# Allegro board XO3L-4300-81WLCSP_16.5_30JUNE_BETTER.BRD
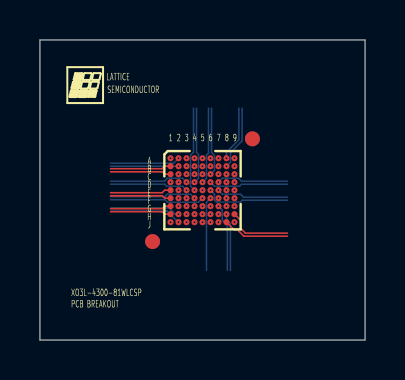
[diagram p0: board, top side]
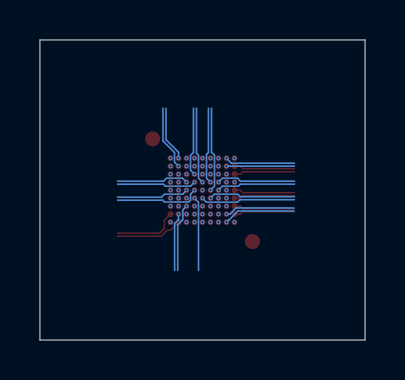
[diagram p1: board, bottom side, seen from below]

Outline 16.28 x 15.02 mm; copper layers: TOP, L2_SIG, L3_PWR/GND, BOTTOM. Coordinates in mm from the lower left corner of the outline.
Outline path: 0,15.02 0,0 16.28,0 16.28,15.02 0,15.02

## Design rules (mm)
net group PB4: nets PB4A PB4B
net group PB7: nets PB7A PB7B
net group PB9: nets PB9A PB9B
net group PB13: nets PB13A PB13B
net group PB15: nets PB15A PB15B
net group PB20: nets PB20A PB20B
net group PB23: nets PB23A PB23B
net group PB24: nets PB24A PB24B
net group PB27: nets PB27A PB27B
net group PB30: nets PB30A PB30B
net group PL4: nets PL4A PL4B
net group PL7: nets PL7A PL7B
net group PL8: nets PL8C PL8D
net group PL15: nets PL15A PL15B
net group PL17: nets PL17A PL17B
net group PL18: nets PL18A PL18B
net group PT9: nets PT9A PT9B
net group PT10: nets PT10A PT10B
net group PT11: nets PT11A PT11B
net group PT13: nets PT13C PT13D
net group PT15: nets PT15C PT15D
net group PT18: nets PT18A PT18B
net group PT19: nets PT19A PT19B
net group PT20: nets PT20C PT20D
net group PT21: nets PT21A PT21B
net group PT22: nets PT22A PT22B
net group PT23: nets PT23C PT23D
net group PT24: nets PT24A PT24B
net group PT25: nets PT25A PT25B
net group PT27: nets PT27A PT27B
net group PT28: nets PT28C PT28D

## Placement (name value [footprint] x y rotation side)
BGA  -  [BGA81N40P9X9_379X369X57B26N]  8.14 7.5 270 top
NOREF  -  []  1.09 11.54 0 top

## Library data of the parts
BGA = BGA81N40P9X9_379X369X57B26N

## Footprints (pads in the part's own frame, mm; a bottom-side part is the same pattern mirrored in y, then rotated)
BGA81N40P9X9_379X369X57B26N
  round 0.75 smd: (-2.57,2.5) (2.57,-2.5)
  round 0.305 smd: A1(-1.6,-1.6) A2(-1.6,-1.2) A3(-1.6,-0.8) A4(-1.6,-0.4) A5(-1.6,0) A6(-1.6,0.4) A7(-1.6,0.8) A8(-1.6,1.2) A9(-1.6,1.6) B1(-1.2,-1.6) B2(-1.2,-1.2) B3(-1.2,-0.8) B4(-1.2,-0.4) B5(-1.2,0) B6(-1.2,0.4) B7(-1.2,0.8) B8(-1.2,1.2) B9(-1.2,1.6) C1(-0.8,-1.6) C2(-0.8,-1.2) C3(-0.8,-0.8) C4(-0.8,-0.4) C5(-0.8,0) C6(-0.8,0.4) C7(-0.8,0.8) C8(-0.8,1.2) C9(-0.8,1.6) D1(-0.4,-1.6) D2(-0.4,-1.2) D3(-0.4,-0.8) D4(-0.4,-0.4) D5(-0.4,0) D6(-0.4,0.4) D7(-0.4,0.8) D8(-0.4,1.2) D9(-0.4,1.6) E1(0,-1.6) E2(0,-1.2) E3(0,-0.8) E4(0,-0.4) E5(0,0) E6(0,0.4) E7(0,0.8) E8(0,1.2) E9(0,1.6) F1(0.4,-1.6) F2(0.4,-1.2) F3(0.4,-0.8) F4(0.4,-0.4) F5(0.4,0) F6(0.4,0.4) F7(0.4,0.8) F8(0.4,1.2) F9(0.4,1.6) G1(0.8,-1.6) G2(0.8,-1.2) G3(0.8,-0.8) G4(0.8,-0.4) G5(0.8,0) G6(0.8,0.4) G7(0.8,0.8) G8(0.8,1.2) G9(0.8,1.6) H1(1.2,-1.6) H2(1.2,-1.2) H3(1.2,-0.8) H4(1.2,-0.4) H5(1.2,0) H6(1.2,0.4) H7(1.2,0.8) H8(1.2,1.2) H9(1.2,1.6) J1(1.6,-1.6) J2(1.6,-1.2) J3(1.6,-0.8) J4(1.6,-0.4) J5(1.6,0) J6(1.6,0.4) J7(1.6,0.8) J8(1.6,1.2) J9(1.6,1.6)

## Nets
GND: BGA.A1 BGA.A9 BGA.E5 BGA.G5 BGA.J1 BGA.J9
VCC: BGA.C4 BGA.D1 BGA.E9 BGA.F3
VCCIO0: BGA.A4 BGA.C5 BGA.C7
VCCIO2: BGA.G6 BGA.J4
VCCIO3: BGA.F9
VCCIO5: BGA.C9
PB4A: BGA.H9
PB4B: BGA.J8
PB7A: BGA.H8
PB7B: BGA.G7
PB9A: BGA.H7
PB9B: BGA.J7
PB13A: BGA.J6
PB13B: BGA.H6
PB15A: BGA.H5
PB15B: BGA.J5
PB20A: BGA.G4
PB20B: BGA.H4
PB23A: BGA.G3
PB23B: BGA.G2
PB24A: BGA.H3
PB24B: BGA.J3
PB27A: BGA.H2
PB27B: BGA.J2
PB30A: BGA.G1
PB30B: BGA.H1
PL4A: BGA.B9
PL4B: BGA.C8
PL5A: BGA.D8
PL7A: BGA.E6
PL7B: BGA.E7
PL8C: BGA.D9
PL8D: BGA.E8
PL15A: BGA.F8
PL15B: BGA.F7
PL16A: BGA.F6
PL17A: BGA.G9
PL17B: BGA.G8
PL18A: BGA.F5
PL18B: BGA.F4
PT9A: BGA.D7
PT9B: BGA.D6
PT10A: BGA.D5
PT10B: BGA.C6
PT11A: BGA.A8
PT11B: BGA.B8
PT13C: BGA.B7
PT13D: BGA.A7
PT15C: BGA.E4
PT15D: BGA.D4
PT18A: BGA.A6
PT18B: BGA.B6
PT19A: BGA.E3
PT19B: BGA.D3
PT20C: BGA.A5
PT20D: BGA.B5
PT21A: BGA.C3
PT21B: BGA.B4
PT22A: BGA.F2
PT22B: BGA.E2
PT23C: BGA.D2
PT23D: BGA.C2
PT24A: BGA.B3
PT24B: BGA.A3
PT25A: BGA.F1
PT25B: BGA.E1
PT27A: BGA.A2
PT27B: BGA.B2
PT28C: BGA.C1
PT28D: BGA.B1

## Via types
v1: diameter 0.203, hole 0.102, TOP to BOTTOM, 73 vias

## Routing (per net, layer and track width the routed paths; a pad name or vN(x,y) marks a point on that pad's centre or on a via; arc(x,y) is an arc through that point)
GND:
  vias: v1(6.54,9.1) v1(6.54,5.9) v1(8.14,7.5) v1(8.14,6.7) v1(9.74,9.1) v1(9.74,5.9)
VCC:
  vias: v1(6.54,7.9) v1(7.34,7.1) v1(7.74,8.3) v1(9.74,7.5)
VCCIO0:
  vias: v1(7.74,9.1) v1(8.14,8.3) v1(8.94,8.3)
VCCIO2:
  vias: v1(7.74,5.9) v1(8.54,6.7)
VCCIO3:
  vias: v1(9.74,7.1)
VCCIO5:
  vias: v1(9.74,8.3)
PB4A: length 3.3
  TOP w0.076: 12.39,5.35 10.29,5.35 10.05,5.59 10.05,5.99 BGA.H9
PB4B: length 3.3
  TOP w0.076: 12.39,5.2 10.21,5.2 9.91,5.5 9.74,5.5 BGA.J8
PB7A: length 2.9
  BOTTOM w0.076: 9.54,3.49 9.54,5.83 9.34,6.03 v1(9.34,6.3)
PB7B: length 3.4
  BOTTOM w0.076: 9.38,3.49 9.38,5.77 9.19,5.97 9.19,5.97 9.13,6.03 9.13,6.22 9.13,6.51 v1(8.94,6.7)
PB9A: length 3.1
  L2_SIG w0.076: 9.74,3.49 9.74,5.5 9.14,6.1 v1(8.94,6.3)
PB9B: length 2.8
  L2_SIG w0.076: 9.59,3.49 9.59,5.42 9.11,5.9 v1(8.94,5.9)
PB13A: length 2.6
  L2_SIG w0.076: v1(8.54,5.9) 8.54,5.53 8.9,5.17 8.9,3.49
PB13B: length 3
  L2_SIG w0.076: 9.05,3.49 9.05,5.24 8.74,5.55 8.74,6.1 v1(8.54,6.3)
PB15A: length 3
  L2_SIG w0.076: v1(8.14,6.3) 8.34,6.1 8.34,5.21 8.54,5.01 8.54,3.49
PB15B: length 2.5
  L2_SIG w0.076: 8.39,3.49 8.39,4.95 8.14,5.2 v1(8.14,5.9)
PB20A: length 3.3
  L2_SIG w0.076: 7.66,3.49 7.66,5.63 7.54,5.76 7.54,6.5 v1(7.74,6.7)
PB20B: length 2.9
  L2_SIG w0.076: v1(7.74,6.3) 7.94,6.1 7.94,5.71 7.82,5.58 7.82,3.49
PB23A: length 3.9
  L2_SIG w0.076: 3.54,6.75 6.62,6.75 6.76,6.9 7.14,6.9 v1(7.34,6.7)
PB23B: length 3.4
  L2_SIG w0.076: v1(6.94,6.7) 6.84,6.6 3.54,6.6
PB24A: length 3
  L2_SIG w0.076: 6.99,3.49 6.99,5.19 7.14,5.34 7.14,6.1 v1(7.34,6.3)
PB24B: length 2.5
  L2_SIG w0.076: v1(7.34,5.9) 7.34,5.33 7.14,5.13 7.14,3.49
PB27A: length 3.5
  BOTTOM w0.076: v1(6.94,6.3) 6.77,6.3 6.46,6.61 3.57,6.61
PB27B: length 3.6
  BOTTOM w0.076: 3.57,6.46 6.36,6.46 6.8,6.02 6.82,6.02 v1(6.94,5.9)
PB30A: length 3.1
  TOP w0.076: 3.54,6.58 6.12,6.58 6.25,6.7 BGA.G1
PB30B: length 3.1
  TOP w0.076: BGA.H1 6.25,6.3 6.12,6.42 3.54,6.42
PL4A: length 2.9
  L2_SIG w0.076: 12.39,9.2 10.24,9.2 v1(9.74,8.7)
PL4B: length 3.4
  L2_SIG w0.076: v1(9.34,8.3) 9.55,8.51 9.82,8.51 10.36,9.05 12.39,9.05
PL5A: length 3.1
  L2_SIG w0.076: 12.39,8.1 9.54,8.1 v1(9.34,7.9)
PL7A: length 4.3
  BOTTOM w0.076: 12.39,7 10.13,7 10.04,6.91 8.83,6.91 8.74,7 8.74,7.3 v1(8.54,7.5)
PL7B: length 3.6
  BOTTOM w0.076: 12.39,7.15 10.19,7.15 10.04,7.3 9.13,7.3 8.94,7.49 v1(8.94,7.5)
PL8C: length 2.8
  L2_SIG w0.076: v1(9.74,7.9) 10.04,7.9 10.29,7.65 12.39,7.65
PL8D: length 3.2
  L2_SIG w0.076: v1(9.34,7.5) 9.54,7.7 10.03,7.7 10.23,7.5 12.39,7.5
PL15A: length 3.2
  L2_SIG w0.076: 12.39,7.05 10.08,7.05 9.93,6.9 9.55,6.9 9.35,7.1 v1(9.34,7.1)
PL15B: length 3.6
  L2_SIG w0.076: 12.39,7.2 10.13,7.2 10.03,7.3 9.14,7.3 v1(8.94,7.1)
PL16A: length 3.7
  BOTTOM w0.076: 8.34,3.49 8.34,6.9 v1(8.54,7.1)
PL17A: length 3
  L2_SIG w0.076: 12.39,6.05 10.2,6.05 9.74,6.52 v1(9.74,6.7)
PL17B: length 3.4
  L2_SIG w0.076: v1(9.34,6.7) 10.14,5.9 12.39,5.9
PL18A: length 4.7
  BOTTOM w0.076: v1(8.14,7.1) 7.94,6.9 6.39,6.9 6.26,7.03 3.54,7.03
PL18B: length 4.3
  BOTTOM w0.076: v1(7.74,7.1) 7.54,7.3 6.38,7.3 6.26,7.18 3.54,7.18
PT9A: length 3.6
  BOTTOM w0.076: v1(8.94,7.9) 9.14,8.1 9.94,8.1 10.09,7.95 12.39,7.95
PT9B: length 4
  BOTTOM w0.076: v1(8.54,7.9) 8.74,7.7 9.99,7.7 10.09,7.8 12.39,7.8
PT10A: length 3.8
  BOTTOM w0.076: v1(8.14,7.9) 8.34,8.1 8.34,9.25 8.44,9.35 8.44,11.6
PT10B: length 3.4
  BOTTOM w0.076: v1(8.54,8.3) 8.74,8.5 8.74,9.24 8.59,9.39 8.59,11.6
PT11A: length 2.8
  BOTTOM w0.076: 9.97,11.6 9.97,10.03 9.34,9.4 v1(9.34,9.1)
PT11B: length 3.2
  BOTTOM w0.076: v1(9.34,8.7) 9.54,8.9 9.54,9.39 10.12,9.96 10.12,11.6
PT13C: length 3.2
  L2_SIG w0.076: 9.59,11.6 9.59,10.04 9.14,9.59 9.14,8.9 v1(8.94,8.7)
PT13D: length 2.7
  L2_SIG w0.076: 9.44,11.6 9.44,10.1 8.94,9.6 v1(8.94,9.1)
PT15C: length 4.2
  BOTTOM w0.076: v1(7.74,7.5) 7.54,7.7 7.54,9.25 7.69,9.4 7.69,11.6
PT15D: length 3.8
  BOTTOM w0.076: 7.84,11.6 7.84,9.39 7.94,9.29 7.94,8.1 v1(7.74,7.9)
PT18A: length 2.7
  L2_SIG w0.076: v1(8.54,9.1) 8.54,9.89 8.94,10.29 8.94,11.6
PT18B: length 3.1
  L2_SIG w0.076: v1(8.54,8.7) 8.74,8.9 8.74,9.87 9.09,10.23 9.09,11.6
PT19A: length 3.9
  BOTTOM w0.076: 3.54,7.8 6.25,7.8 6.35,7.7 7.14,7.7 v1(7.34,7.5)
PT19B: length 3.9
  BOTTOM w0.076: 3.54,7.95 6.24,7.95 6.39,8.1 7.14,8.1 v1(7.34,7.9)
PT20C: length 2.6
  L2_SIG w0.076: v1(8.14,9.1) 8.14,9.86 7.81,10.19 7.81,11.6
PT20D: length 3.1
  L2_SIG w0.076: 7.96,11.6 7.96,10.25 8.34,9.87 8.34,8.9 v1(8.14,8.7)
PT21A: length 3.5
  L2_SIG w0.076: v1(7.34,8.3) 7.54,8.5 7.54,9.78 7.24,10.08 7.24,11.6
PT21B: length 3.2
  L2_SIG w0.076: 7.39,11.6 7.39,10.14 7.74,9.79 7.74,9.4 7.94,9.2 7.94,8.86 7.78,8.7 v1(7.74,8.7)
PT22A: length 3.5
  L2_SIG w0.076: v1(6.94,7.1) 6.71,7.1 6.59,7.22 3.54,7.22
PT22B: length 3.5
  L2_SIG w0.076: 3.54,7.37 6.59,7.37 6.72,7.5 v1(6.94,7.5)
PT23C: length 3.7
  L2_SIG w0.076: v1(6.94,7.9) 6.31,8.53 3.54,8.53
PT23D: length 3.6
  L2_SIG w0.076: 3.54,8.68 6.37,8.68 6.76,8.3 v1(6.94,8.3)
PT24A: length 3.2
  L2_SIG w0.076: v1(7.34,8.7) 7.14,8.9 7.14,9.43 6.64,9.93 6.64,11.6
PT24B: length 2.7
  L2_SIG w0.076: v1(7.34,9.1) 7.34,9.44 6.79,9.99 6.79,11.6
PT25A: length 3.1
  TOP w0.076: 3.54,7.22 6.12,7.22 6.25,7.1 BGA.F1
PT25B: length 3.1
  TOP w0.076: BGA.E1 6.25,7.5 6.12,7.38 3.54,7.38
PT27A: length 3.5
  BOTTOM w0.076: 3.54,8.85 6.69,8.85 v1(6.94,9.1)
PT27B: length 3.4
  BOTTOM w0.076: v1(6.94,8.7) 3.54,8.7
PT28C: length 3.1
  TOP w0.076: BGA.C1 6.25,8.3 6.12,8.42 3.54,8.42
PT28D: length 3.1
  TOP w0.076: BGA.B1 6.25,8.7 6.12,8.58 3.54,8.58

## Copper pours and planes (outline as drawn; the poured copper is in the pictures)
GND on L3_PWR/GND: 8.39,6.95 8.24,6.8 8.24,6.35 8.09,6.2 7.39,6.2 7.24,6.05 7.24,5.5 6.14,5.5 6.14,9.5 10.35,9.5 10.35,8.2 9.24,8.2 9.24,9.1 9.04,9.3 7.54,9.3 7.39,9.15 7.39,8.55 6.64,8.55 6.34,8.25 6.34,6.8 6.49,6.65 7.59,6.65 7.74,6.8 7.74,7.55 7.79,7.6 9.16,7.6 9.41,7.35 9.41,6.94 9.71,6.64 10.35,6.64 10.35,5.5 9.04,5.5 9.04,6.8 8.89,6.95
VCC on L3_PWR/GND: 6.69,8.45 7.79,8.45 7.89,8.35 7.89,8.25 8.04,8.1 10.35,8.12 10.35,7.37 9.52,7.37 9.19,7.7 7.74,7.7 7.64,7.6 7.64,6.85 7.54,6.75 6.54,6.75 6.44,6.85 6.44,8.2
VCCIO0 on L3_PWR/GND: 7.54,9.2 7.49,9.15 7.49,8.55 7.84,8.55 7.99,8.4 7.99,8.3 8.09,8.2 9.14,8.2 9.14,9.05 8.99,9.2
VCCIO2 on L3_PWR/GND: 8.34,6.75 8.44,6.85 8.84,6.85 8.94,6.75 8.94,5.5 7.34,5.5 7.34,6 7.44,6.1 8.14,6.1 8.34,6.3

Small or netless copper shapes (teardrops, artwork), in the pictures only: 1 on L3_PWR/GND

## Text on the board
User.Comments: ASP | 06-27-14 | DWG NO: | XO3L-4300-81WLCSP | REVISION | 1.1 | SHEET | 1 | OF | XO3L-4300-81WLCSP PCB BREAKOUT | LATTICE SEMICONDUCTOR CORPORATION
Ref Des/Silkscreen Top: XO3L-4300-81WLCSP | PCB BREAKOUT | LATTICE | SEMICONDUCTOR | A | B | C | D | E | F | G | H | J | 1 | 2 | 3 | 4 | 5 | 6 | 7 | 8 | 9
PAGE_OUTLINE: 354.33 x 354.33 | 149.49 x 145.39 | SPECIAL INSTRUCTIONS: | USE 1/2 OUNCE COPPER FOR BOTH INTERNAL AND EXTERNAL LAYERS | VIAS ARE TO BE NON-CONDUCTIVE EPOXY FILLED | PLANARIZE AT TOP AND BOTTOM | BOARD THICKNESS IS 62MILS | SIGNAL         (L2) | POWER/GND PLANE (L3) | PRIMARY SIDE   (L1) | SECONDARY SIDE (L4) | SECONDARY SILKSCREEN | SECONDARY SOLDERMASK | PRIMARY SOLDERMASK | PRIMARY SILKSCREEN | DESIGNED BY: | APPROVED BY: | SIGNATURES         DATE | REV | 1 | INITIAL RELEASE | ESCAPE VIA DRILL | TRACE WIDTH/SPACE | ESCAPE VIA PAD | ARRAY SIZE | BGA LAND OPENING | BGA LAND PAD | PACKAGE SIZE | PITCH | DESCRIPTION | 3.797x3.693 | 0.0762 | 0.0584 | 0.1016 | 0.2032 | 0.3048 | 9 X 9 | 0.40 | MM | MM/DD/YYYY | DATE | 12.00 | 3/2.3 | 15.748 | 8.00 | MILS | 4.00 | APPROVED | XXXXXXXXX | 4 LAYER STACKUP | PCB BREAKOUT DETAILS | REVISION
PLACE_BOUND_TOP: FIGURE | SIZE | 0.1 | ALL UNITS ARE IN MILLIMETERS | SIZE MM | PLATED | QTY | 22 | DRILL CHART: TOP to L4_IO
DISPLAY_TOP: FIGURE | SIZE | 0.1 | ALL UNITS ARE IN MILLIMETERS | SIZE MM | PLATED | QTY | 26 | DRILL CHART: TOP to BOTTOM
DEVICE_TYPE_TOP: FIGURE | SIZE | 0.1 | ALL UNITS ARE IN MILLIMETERS | SIZE MM | PLATED | QTY | 25 | DRILL CHART: TOP to L3_IO
